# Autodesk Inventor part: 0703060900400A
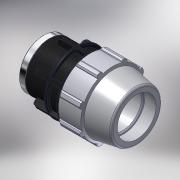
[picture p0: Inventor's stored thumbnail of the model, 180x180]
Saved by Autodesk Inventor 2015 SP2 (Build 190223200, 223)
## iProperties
Created: 2017-02
Part Number: 0703060900400A
Material: PVC-Piping
Description: PLASSON FEMALE ADAPTOR 90-4"
Document SubType Name: Modeling
Designer: KIM
Mass: 92.6774 g
Surface Area: 199.44 cm^2
Volume: 66.1981 cm^3
Density: 1.4 g/cm^3
Appearance: PTFE
Author: KIM
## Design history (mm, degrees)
derived "87030.ipt"
feature "Solid1::87030.ipt"
tag "TaggingFeature1"
body "Solid1"
other parameters: "d4" = 34.71429, "d5" = 60.75, "d7" = 154, "d9" = 34.71429, "d11" = 6.94286, "d12" = 123.2, "d13" = 120 deg, "d14" = 143, "d15" = 8 deg, "d16" = 138.6, "d18" = 5.5, "d19" = 35 deg, "d20" = 17.5 deg, "d21" = 143.22, "d23" = 0, "d25" = 360 deg, "d27" = 3.08, "d34" = 7.7, "d35" = 72.9, "d36" = 0, "d42" = 60.75, "d43" = 4.62, "d46" = 3.3, "d49" = 183, "d51" = 243, "d53" = 2.2, "d55" = 360 deg, "d61" = 52, "d62" = 88, "d63" = 110.072, "d64" = 81, "d65" = 7.7, "d69" = 123.2, "d70" = 3.85, "d71" = 12.6, "d72" = 0.5, "d73" = 1, "E_" = 154, "H_" = 243, "l_" = 183, "l_2" = 52, "Rp_Rc_" = 110.072
